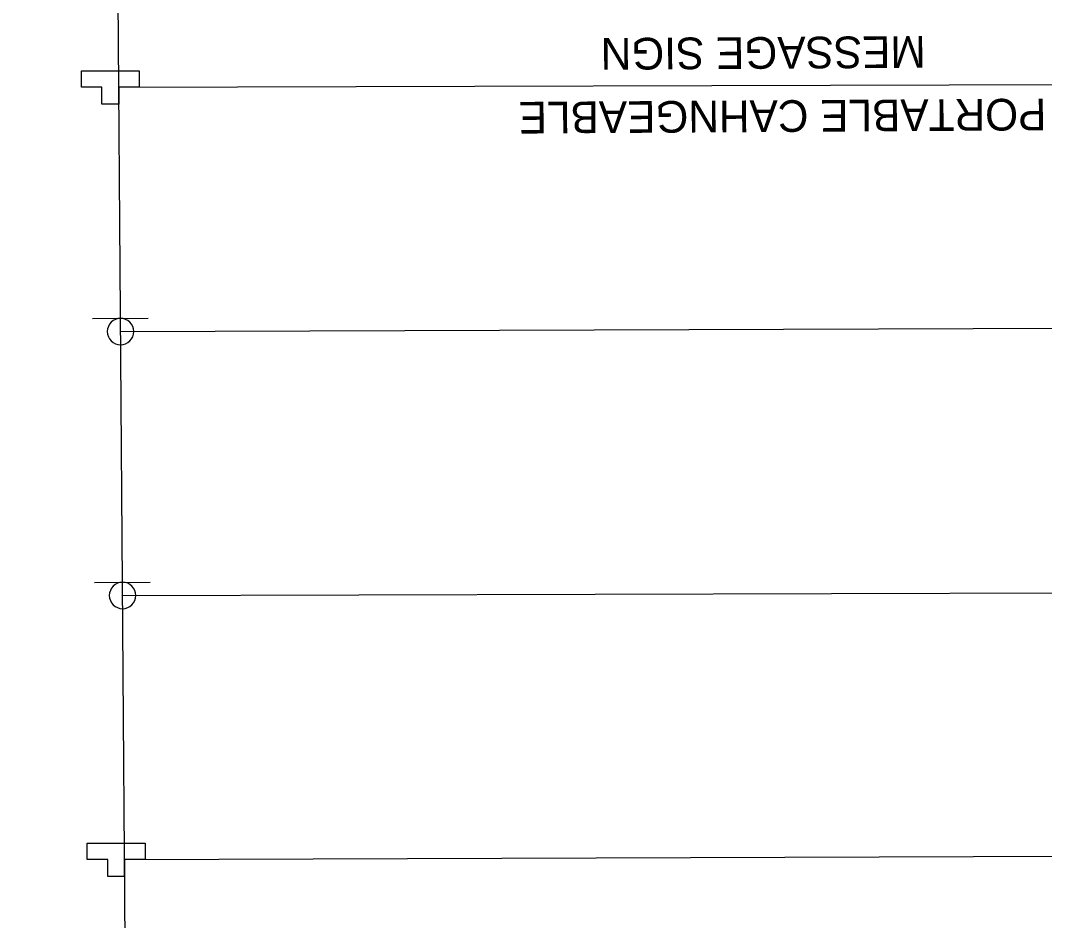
# Model space of a CAD drawing. Extents: x 2135767 to 2151731, y 141839 to 175894.
# Drawn here: x 2140585.2 to 2140779, y 170737.2 to 170907.6 of the extents above; entities that cross this region are included whole.
import ezdxf

# ---------------------------------------------------------------- set-up
doc = ezdxf.new("R2010")
doc.units = 0
for name, color, linetype in [('Default', 7, 'Continuous'), ('PR_Dimensions_Phase', 7, 'Continuous'), ('PR_Phasing_Detour_1', 7, 'Continuous'), ('PR_Traffic_Control_Devices_Temp', 7, 'Continuous')]:
    doc.layers.add(name, color=color, linetype=linetype)

# ---------------------------------------------------------------- blocks, each defined once
blk = doc.blocks.new('PR-TCSIGN_rev')
at = {"layer": 'Default'}
blk.add_lwpolyline([(-5.47, 0), (-1.58, 0), (-1.58, -3.22), (1.58, -3.22), (1.58, 0), (5.47, 0), (5.47, 3.06), (-5.47, 3.06)], close=True, dxfattribs=at)
blk.add_lwpolyline([(1.58, 0), (5.47, 0), (5.47, 3.06), (-5.47, 3.06), (-5.47, 0), (-1.58, 0), (-1.58, -3.22), (1.58, -3.22), (1.58, 0)], dxfattribs=at)
blk = doc.blocks.new('PR-TCSIGN')
at = {"layer": 'Default'}
blk.add_line((17.82, 8.47), (-17.82, 8.47), dxfattribs=at)
blk.add_circle((0, 0), 8.47, dxfattribs=at)

msp = doc.modelspace()

# ---------------------------------------------------------------- linework, layer by layer
at = {"layer": 'PR_Dimensions_Phase'}
for p, q in [((2140603.75, 170895), (2140847.16, 170895.7)), ((2140604.1, 170848.71), (2140901.04, 170849.76)), ((2140604.48, 170798.72), (2140816.39, 170799.33)), ((2140604.85, 170748.74), (2140899.57, 170749.75))]:
    msp.add_line(p, q, dxfattribs=at)
at = {"layer": 'PR_Phasing_Detour_1'}
msp.add_circle((2140069.54, 171591.41), 4302.23, dxfattribs=at)
at = {"layer": 'PR_Traffic_Control_Devices_Temp'}
msp.add_line((2140607.23, 170431.76), (2140602.86, 171013.91), dxfattribs=at)

# ---------------------------------------------------------------- block references
at = {"layer": 'PR_Traffic_Control_Devices_Temp', "yscale": -1, "rotation": -180}
for p in [(2140602.17, 170895), (2140603.27, 170748.74)]:
    msp.add_blockref('PR-TCSIGN_rev', p, dxfattribs=at)
at = {"layer": 'PR_Traffic_Control_Devices_Temp', "xscale": 0.2952750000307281, "yscale": -0.2952750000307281, "rotation": -179.6349826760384}
for p in [(2140604.1, 170848.71), (2140604.48, 170798.72)]:
    msp.add_blockref('PR-TCSIGN', p, dxfattribs=at)

# ---------------------------------------------------------------- texts
at = {"layer": 'Default'}
for s, p in [('MESSAGE SIGN', (2140756.5, 170904.68)), ('PORTABLE CAHNGEABLE', (2140779.34, 170892.83))]:
    msp.add_text(s, height=6, rotation=180.365, dxfattribs=at).set_placement(p)

doc.saveas('drawing.dxf')
